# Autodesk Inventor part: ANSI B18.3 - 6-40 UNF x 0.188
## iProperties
IsCustomPart: 0
Created: 2008-02
Part Number: ANSI B18.3 - 6-40 UNF x 0.188
Material: Steel, Mild
Description: Hexagon Socket Set Screw - Flat Point
Document SubType Name: Modeling
Standard: ANSI B18.3
Standard Revision: 2003
Standards Organization: ANSI
Language: en-US
Size Designation: 6-40 UNF x 0.188
Categories: <MemberInstance><Categories><Category DisplayName="Fasteners" InternalName="e4da775c-781d-43d5-af7c-5136215cf5a6" Mnemonic="FSTN"><Category DisplayName="Bolts"
Density: 7.86 g/cm^3
Mass: 0.312247 g
Surface Area: 0.781327 cm^2
Volume: 0.0397261 cm^3
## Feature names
1. Body [Revolution]
2. Chamfer1
3. Slot [Extrusion]
4. Chamfer2
